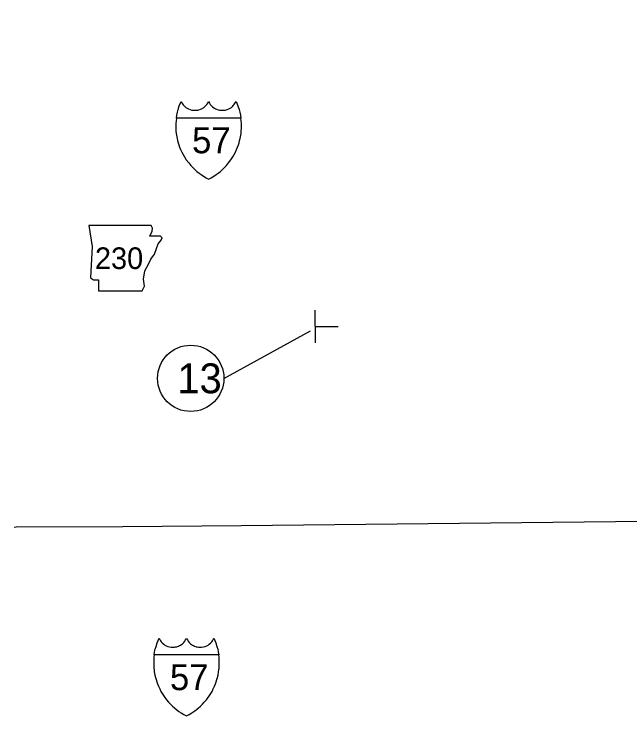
# Model space of a CAD drawing. Extents: x -31818 to 1228740, y -23925 to 152440.
# Drawn here: x -31787.28 to -31762.51, y -23864.25 to -23836.03 of the extents above; entities that cross this region are included whole.
import ezdxf

# ---------------------------------------------------------------- set-up
doc = ezdxf.new("R2010")
doc.units = 0
for name, color, linetype in [('21', 7, 'Continuous'), ('23', 7, 'Continuous'), ('8', 7, 'Continuous'), ('Level 3', 7, 'Continuous'), ('Level 8', 7, 'Continuous'), ('shading', 7, 'Continuous')]:
    doc.layers.add(name, color=color, linetype=linetype)

msp = doc.modelspace()

# ---------------------------------------------------------------- linework, layer by layer
at = {"layer": '21'}
msp.add_lwpolyline([(-31784.271, -23844.537), (-31784.145, -23845.373), (-31784.201, -23846.642), (-31784.09, -23846.711), (-31783.88, -23846.711), (-31783.88, -23847.157), (-31782.124, -23847.157), (-31782.04, -23846.976), (-31782.068, -23846.683), (-31782.026, -23846.349), (-31781.873, -23846.084), (-31781.776, -23845.889), (-31781.636, -23845.68), (-31781.553, -23845.457), (-31781.483, -23845.275), (-31781.357, -23845.122), (-31781.329, -23845.025), (-31781.385, -23844.955), (-31781.817, -23844.955), (-31781.72, -23844.76), (-31781.706, -23844.634), (-31781.764, -23844.538)], close=True, dxfattribs=at)
at = {"layer": '23'}
for points in [[(-31780.753, -23840.212), (-31780.735, -23840.092), (-31780.711, -23839.979), (-31780.68, -23839.869), (-31780.635, -23839.728), (-31780.559, -23839.544), (-31780.5, -23839.642), (-31780.475, -23839.682), (-31780.449, -23839.715), (-31780.417, -23839.746), (-31780.37, -23839.786), (-31780.322, -23839.82), (-31780.27, -23839.849), (-31780.202, -23839.875), (-31780.135, -23839.891), (-31780.064, -23839.901), (-31779.989, -23839.903), (-31779.935, -23839.899), (-31779.89, -23839.893), (-31779.842, -23839.883), (-31779.775, -23839.858), (-31779.732, -23839.84), (-31779.695, -23839.82), (-31779.66, -23839.796), (-31779.617, -23839.764), (-31779.562, -23839.709), (-31779.523, -23839.662), (-31779.491, -23839.609), (-31779.455, -23839.547)], [(-31779.455, -23839.547), (-31779.419, -23839.609), (-31779.387, -23839.662), (-31779.348, -23839.709), (-31779.293, -23839.764), (-31779.25, -23839.796), (-31779.215, -23839.82), (-31779.178, -23839.84), (-31779.135, -23839.858), (-31779.068, -23839.883), (-31779.02, -23839.893), (-31778.975, -23839.899), (-31778.921, -23839.903), (-31778.845, -23839.901), (-31778.774, -23839.891), (-31778.708, -23839.875), (-31778.64, -23839.849), (-31778.588, -23839.82), (-31778.54, -23839.786), (-31778.493, -23839.746), (-31778.461, -23839.715), (-31778.435, -23839.682), (-31778.41, -23839.642), (-31778.351, -23839.544), (-31778.275, -23839.728), (-31778.23, -23839.869), (-31778.199, -23839.979), (-31778.175, -23840.092), (-31778.157, -23840.212)], [(-31780.751, -23840.212), (-31780.764, -23840.319), (-31780.772, -23840.43), (-31780.775, -23840.532), (-31780.773, -23840.626), (-31780.768, -23840.734), (-31780.758, -23840.828), (-31780.749, -23840.897), (-31780.724, -23841.029), (-31780.703, -23841.121), (-31780.679, -23841.205), (-31780.652, -23841.292), (-31780.621, -23841.378), (-31780.583, -23841.473), (-31780.533, -23841.581), (-31780.482, -23841.679), (-31780.431, -23841.767), (-31780.352, -23841.89), (-31780.254, -23842.02), (-31780.173, -23842.117), (-31780.101, -23842.194), (-31780.023, -23842.272), (-31779.928, -23842.356), (-31779.841, -23842.426), (-31779.757, -23842.487), (-31779.666, -23842.548), (-31779.558, -23842.612), (-31779.455, -23842.667)], [(-31778.157, -23840.212), (-31780.753, -23840.212)], [(-31779.455, -23842.667), (-31779.352, -23842.612), (-31779.244, -23842.548), (-31779.153, -23842.487), (-31779.069, -23842.426), (-31778.982, -23842.356), (-31778.887, -23842.272), (-31778.809, -23842.194), (-31778.737, -23842.117), (-31778.655, -23842.02), (-31778.558, -23841.89), (-31778.479, -23841.767), (-31778.428, -23841.679), (-31778.377, -23841.581), (-31778.327, -23841.473), (-31778.289, -23841.378), (-31778.258, -23841.292), (-31778.23, -23841.205), (-31778.207, -23841.121), (-31778.186, -23841.029), (-31778.161, -23840.897), (-31778.152, -23840.828), (-31778.142, -23840.734), (-31778.136, -23840.626), (-31778.135, -23840.532), (-31778.138, -23840.43), (-31778.146, -23840.319), (-31778.159, -23840.212), (-31780.751, -23840.212)], [(-31781.643, -23861.792), (-31781.625, -23861.672), (-31781.601, -23861.559), (-31781.57, -23861.449), (-31781.526, -23861.309), (-31781.449, -23861.124), (-31781.391, -23861.222), (-31781.365, -23861.263), (-31781.339, -23861.296), (-31781.308, -23861.326), (-31781.261, -23861.366), (-31781.213, -23861.4), (-31781.16, -23861.43), (-31781.093, -23861.455), (-31781.026, -23861.472), (-31780.955, -23861.481), (-31780.88, -23861.483), (-31780.825, -23861.479), (-31780.781, -23861.474), (-31780.733, -23861.463), (-31780.666, -23861.439), (-31780.622, -23861.42), (-31780.586, -23861.401), (-31780.55, -23861.377), (-31780.508, -23861.344), (-31780.452, -23861.29), (-31780.414, -23861.242), (-31780.381, -23861.19), (-31780.346, -23861.128)], [(-31780.346, -23861.128), (-31780.31, -23861.19), (-31780.277, -23861.242), (-31780.239, -23861.29), (-31780.183, -23861.344), (-31780.141, -23861.377), (-31780.105, -23861.401), (-31780.069, -23861.42), (-31780.025, -23861.439), (-31779.958, -23861.463), (-31779.91, -23861.474), (-31779.866, -23861.479), (-31779.811, -23861.483), (-31779.736, -23861.481), (-31779.665, -23861.472), (-31779.598, -23861.455), (-31779.531, -23861.43), (-31779.478, -23861.4), (-31779.43, -23861.366), (-31779.383, -23861.326), (-31779.352, -23861.296), (-31779.326, -23861.263), (-31779.3, -23861.222), (-31779.242, -23861.124), (-31779.165, -23861.309), (-31779.121, -23861.449), (-31779.09, -23861.559), (-31779.066, -23861.672), (-31779.048, -23861.792)], [(-31781.642, -23861.792), (-31781.654, -23861.899), (-31781.662, -23862.01), (-31781.665, -23862.112), (-31781.664, -23862.206), (-31781.658, -23862.315), (-31781.649, -23862.408), (-31781.639, -23862.477), (-31781.615, -23862.609), (-31781.593, -23862.701), (-31781.57, -23862.785), (-31781.543, -23862.872), (-31781.512, -23862.959), (-31781.473, -23863.053), (-31781.423, -23863.162), (-31781.373, -23863.259), (-31781.322, -23863.348), (-31781.242, -23863.47), (-31781.145, -23863.601), (-31781.063, -23863.698), (-31780.992, -23863.775), (-31780.913, -23863.852), (-31780.819, -23863.936), (-31780.731, -23864.007), (-31780.648, -23864.068), (-31780.557, -23864.128), (-31780.449, -23864.193), (-31780.346, -23864.247)], [(-31779.048, -23861.792), (-31781.643, -23861.792)], [(-31780.346, -23864.247), (-31780.242, -23864.193), (-31780.134, -23864.128), (-31780.043, -23864.068), (-31779.96, -23864.007), (-31779.872, -23863.936), (-31779.778, -23863.852), (-31779.699, -23863.775), (-31779.628, -23863.698), (-31779.546, -23863.601), (-31779.449, -23863.47), (-31779.369, -23863.348), (-31779.318, -23863.259), (-31779.268, -23863.162), (-31779.218, -23863.053), (-31779.179, -23862.959), (-31779.148, -23862.872), (-31779.121, -23862.785), (-31779.098, -23862.701), (-31779.076, -23862.609), (-31779.052, -23862.477), (-31779.042, -23862.408), (-31779.033, -23862.315), (-31779.027, -23862.206), (-31779.026, -23862.112), (-31779.029, -23862.01), (-31779.037, -23861.899), (-31779.049, -23861.792), (-31781.642, -23861.792)]]:
    msp.add_lwpolyline(points, dxfattribs=at)
at = {"layer": '8'}
msp.add_line((-31778.841, -23850.676), (-31775.363, -23848.761), dxfattribs=at)
msp.add_lwpolyline([(-31787.282, -23856.652), (-31787.197, -23856.651), (-31787.197, -23856.651), (-31782.901, -23856.634), (-31778.143, -23856.591), (-31750.551, -23856.302), (-31741.336, -23856.095), (-31715.54, -23856.002), (-31715.99, -23839.147), (-31715.935, -23838.287), (-31716.228, -23836.032)], dxfattribs=at)
at = {"layer": 'Level 3'}
for p, q in [((-31775.149, -23849.25), (-31775.165, -23847.938)), ((-31775.138, -23848.597), (-31774.242, -23848.586))]:
    msp.add_line(p, q, dxfattribs=at)
at = {"layer": 'Level 8'}
msp.add_circle((-31780.174, -23850.676), 1.333, dxfattribs=at)
at = {"layer": 'shading'}
msp.add_circle((-31780.174, -23850.676), 1.333, dxfattribs=at)

# ---------------------------------------------------------------- texts
at = {"layer": '21'}
msp.add_text('230', height=0.8701, dxfattribs=at).set_placement((-31784.028, -23846.282))
at = {"layer": '23'}
for p in [(-31780.121, -23841.629), (-31781.011, -23863.21)]:
    msp.add_text('57', height=1.0441, dxfattribs=at).set_placement(p)
at = {"layer": 'Level 8'}
msp.add_text('13', height=1.2, dxfattribs=at).set_placement((-31780.712, -23851.276))

doc.saveas('drawing.dxf')
